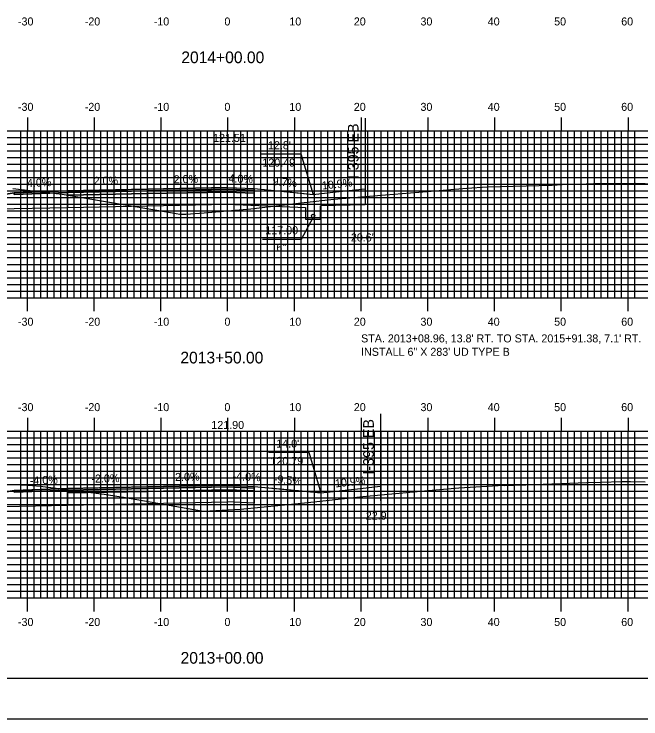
# Model space of a CAD drawing. Extents: x 854287 to 854631, y 366605 to 366825.
# Drawn here: x 854421 to 854515, y 366604.9 to 366710.6 of the extents above; entities that cross this region are included whole.
import ezdxf

# ---------------------------------------------------------------- set-up
doc = ezdxf.new("R2010")
doc.units = 0
for name, color, linetype in [('ANNOTATION', 7, 'Continuous'), ('BORDER', 7, 'Continuous'), ('D_Roadway_Centerline', 7, 'Continuous'), ('D_Roadway_Centerline_Text', 7, 'Continuous'), ('D_Roadway_Edge_Shoulder', 7, 'Continuous'), ('D_Roadway_Edge_TW', 7, 'Continuous'), ('D_Roadway_Pavement', 7, 'Continuous'), ('D_Roadway_SubGrade', 7, 'Continuous'), ('D_Text_Standard', 7, 'Continuous'), ('H_V ANNOTATION', 7, 'Continuous'), ('JUNK', 7, 'Continuous'), ('M_Roadway_Centerline', 7, 'Continuous'), ('MAJOR', 7, 'Continuous'), ('MINOR', 7, 'Continuous'), ('PDRAIN', 7, 'Continuous'), ('PLOT BOUNDARY', 7, 'Continuous'), ('S_Roadway_Centerline', 7, 'Continuous')]:
    doc.layers.add(name, color=color, linetype=linetype)

msp = doc.modelspace()

# ---------------------------------------------------------------- linework, layer by layer
at = {"layer": 'ANNOTATION'}
for points in [[(854458.14, 366689.63), (854464.02, 366689.63), (854465.84, 366683.55)], [(854458.27, 366676.85), (854464.11, 366676.85), (854465.84, 366680.06)], [(854459.19, 366644.93), (854465.21, 366644.93), (854467.02, 366638.84)]]:
    msp.add_lwpolyline(points, dxfattribs=at)
at = {"layer": 'BORDER'}
msp.add_lwpolyline([(854303.44, 366611.06), (854623.44, 366611.06), (854623.44, 366821.06), (854303.44, 366821.06)], close=True, dxfattribs=at)
at = {"layer": 'D_Roadway_Centerline'}
msp.add_line((854453.04, 366682.07), (854464.72, 366681.6), dxfattribs=at)
for points in [[(854403.95, 366680.92), (854421.04, 366683.77), (854421.04, 366683.77), (854429.03, 366684.08), (854429.04, 366684.09), (854438.03, 366684.26), (854441.04, 366684.33), (854441.05, 366684.33), (854453.04, 366684.57), (854457.04, 366684.41), (854463.16, 366683.81), (854465.84, 366683.55)], [(854457.04, 366684.41), (854465.84, 366683.55)], [(854465.84, 366683.55), (854468.83, 366683.87), (854473.67, 366684.4)], [(854473.67, 366681.98), (854466.97, 366681.84)], [(854403.95, 366636.3), (854403.96, 366636.3), (854417.85, 366638.62), (854421.04, 366639.15), (854422.54, 366639.21), (854429.04, 366639.47), (854429.04, 366639.47), (854435.92, 366639.61), (854441.04, 366639.71), (854441.05, 366639.71), (854453.04, 366639.95), (854454.91, 366639.88), (854457.04, 366639.79), (854457.05, 366639.79), (854467.03, 366638.84)], [(854457.04, 366639.79), (854467.01, 366638.85)], [(854467.02, 366638.84), (854472.07, 366639.39), (854475.95, 366639.82)]]:
    msp.add_lwpolyline(points, dxfattribs=at)
at = {"layer": 'D_Roadway_Edge_Shoulder'}
for points in [[(854453.04, 366684.57), (854457.04, 366684.41), (854457.04, 366684.16), (854453.04, 366684.32)], [(854429.04, 366684.09), (854421.04, 366683.77), (854421.04, 366683.52), (854429.04, 366683.84)], [(854429.04, 366639.47), (854421.04, 366639.15), (854421.04, 366638.9), (854429.04, 366639.22)], [(854453.04, 366639.95), (854457.04, 366639.79), (854457.04, 366639.54), (854453.04, 366639.7)]]:
    msp.add_lwpolyline(points, close=True, dxfattribs=at)
at = {"layer": 'D_Roadway_Edge_TW'}
for points in [[(854441.04, 366684.33), (854429.04, 366684.09), (854429.04, 366683.84), (854441.04, 366684.08)], [(854453.04, 366684.57), (854441.04, 366684.33), (854441.04, 366684.08), (854453.04, 366684.32)], [(854441.04, 366639.71), (854429.04, 366639.47), (854429.04, 366639.22), (854441.04, 366639.46)], [(854453.04, 366639.95), (854441.04, 366639.71), (854441.04, 366639.46), (854453.04, 366639.7)]]:
    msp.add_lwpolyline(points, close=True, dxfattribs=at)
at = {"layer": 'D_Roadway_Pavement'}
for points in [[(854441.04, 366684.08), (854429.04, 366683.84), (854429.04, 366683.42), (854441.04, 366683.66)], [(854429.04, 366683.84), (854429.04, 366683.42), (854429.04, 366683.42)], [(854453.04, 366684.32), (854441.04, 366684.08), (854441.04, 366683.66), (854453.04, 366683.9)], [(854453.04, 366684.32), (854457.04, 366684.16), (854457.04, 366683.74), (854453.04, 366683.9)], [(854441.04, 366639.46), (854429.04, 366639.22), (854429.04, 366638.8), (854441.04, 366639.04)], [(854429.04, 366639.22), (854429.04, 366638.8), (854429.04, 366638.8)], [(854453.04, 366639.7), (854441.04, 366639.46), (854441.04, 366639.04), (854453.04, 366639.28)], [(854453.04, 366639.7), (854457.04, 366639.54), (854457.04, 366639.12), (854453.04, 366639.28)]]:
    msp.add_lwpolyline(points, close=True, dxfattribs=at)
for points in [[(854441.04, 366684.08), (854441.04, 366683.66)], [(854441.04, 366639.46), (854441.04, 366639.04)]]:
    msp.add_lwpolyline(points, dxfattribs=at)
at = {"layer": 'D_Roadway_SubGrade'}
for p, q in [((854473.67, 366694.95), (854473.67, 366681.98)), ((854475.95, 366650.64), (854475.95, 366639.82))]:
    msp.add_line(p, q, dxfattribs=at)
for points in [[(854453.04, 366683.9), (854457.04, 366683.74), (854457.04, 366684.16), (854457.04, 366684.41), (854457.04, 366681.91), (854453.04, 366682.07)], [(854429.04, 366683.42), (854429.04, 366683.42), (854429.04, 366683.84), (854421.04, 366683.52), (854421.04, 366683.77), (854405.09, 366681.11), (854429.04, 366681.59)], [(854441.04, 366683.66), (854429.04, 366683.42), (854429.04, 366681.59), (854441.04, 366681.83)], [(854453.04, 366683.9), (854441.04, 366683.66), (854441.04, 366681.83), (854453.04, 366682.07)], [(854429.04, 366638.8), (854429.04, 366638.8), (854429.04, 366639.22), (854421.04, 366638.9), (854421.04, 366639.15), (854405.09, 366636.49), (854429.04, 366636.97)], [(854441.04, 366639.04), (854429.04, 366638.8), (854429.04, 366636.97), (854441.04, 366637.21)], [(854453.04, 366639.28), (854441.04, 366639.04), (854441.04, 366637.21), (854453.04, 366637.45)], [(854453.04, 366639.28), (854457.04, 366639.12), (854457.04, 366639.54), (854457.04, 366639.79), (854457.04, 366637.29), (854453.04, 366637.45)]]:
    msp.add_lwpolyline(points, close=True, dxfattribs=at)
at = {"layer": 'JUNK'}
msp.add_line((854475.95, 366639.82), (854475.95, 366637.61), dxfattribs=at)
at = {"layer": 'MAJOR'}
for p, q in [((854423.04, 366695.06), (854423.04, 366693.06)), ((854433.04, 366695.06), (854433.04, 366693.06)), ((854443.04, 366695.06), (854443.04, 366693.06)), ((854453.04, 366695.06), (854453.04, 366693.06)), ((854463.04, 366695.06), (854463.04, 366693.06)), ((854473.04, 366695.06), (854473.04, 366693.06)), ((854483.04, 366695.06), (854483.04, 366693.06)), ((854493.04, 366695.06), (854493.04, 366693.06)), ((854503.04, 366695.06), (854503.04, 366693.06)), ((854513.04, 366695.06), (854513.04, 366693.06)), ((854313.04, 366693.06), (854593.04, 366693.06)), ((854313.04, 366693.06), (854593.04, 366693.06)), ((854423.04, 366668.06), (854423.04, 366693.06)), ((854433.04, 366668.06), (854433.04, 366693.06)), ((854443.04, 366668.06), (854443.04, 366693.06)), ((854453.04, 366668.06), (854453.04, 366693.06)), ((854463.04, 366668.06), (854463.04, 366693.06)), ((854473.04, 366668.06), (854473.04, 366693.06)), ((854483.04, 366668.06), (854483.04, 366693.06)), ((854493.04, 366668.06), (854493.04, 366693.06)), ((854503.04, 366668.06), (854503.04, 366693.06)), ((854513.04, 366668.06), (854513.04, 366693.06)), ((854313.04, 366688.06), (854593.04, 366688.06)), ((854313.04, 366683.06), (854593.04, 366683.06)), ((854313.04, 366678.06), (854593.04, 366678.06)), ((854313.04, 366673.06), (854593.04, 366673.06)), ((854313.04, 366668.06), (854593.04, 366668.06)), ((854313.04, 366668.06), (854593.04, 366668.06)), ((854423.04, 366666.05), (854423.04, 366668.06)), ((854433.04, 366666.05), (854433.04, 366668.06)), ((854443.04, 366666.05), (854443.04, 366668.06)), ((854453.04, 366666.05), (854453.04, 366668.06)), ((854463.04, 366666.05), (854463.04, 366668.06)), ((854473.04, 366666.05), (854473.04, 366668.06)), ((854483.04, 366666.05), (854483.04, 366668.06)), ((854493.04, 366666.05), (854493.04, 366668.06)), ((854503.04, 366666.05), (854503.04, 366668.06)), ((854513.04, 366666.05), (854513.04, 366668.06)), ((854423.04, 366650.06), (854423.04, 366648.06)), ((854433.04, 366650.06), (854433.04, 366648.06)), ((854443.04, 366650.06), (854443.04, 366648.06)), ((854453.04, 366650.06), (854453.04, 366648.06)), ((854463.04, 366650.06), (854463.04, 366648.06)), ((854473.04, 366650.06), (854473.04, 366648.06)), ((854483.04, 366650.06), (854483.04, 366648.06)), ((854493.04, 366650.06), (854493.04, 366648.06)), ((854503.04, 366650.06), (854503.04, 366648.06)), ((854513.04, 366650.06), (854513.04, 366648.06)), ((854313.04, 366648.06), (854593.04, 366648.06)), ((854313.04, 366648.06), (854593.04, 366648.06)), ((854423.04, 366623.06), (854423.04, 366648.06)), ((854433.04, 366623.06), (854433.04, 366648.06)), ((854443.04, 366623.06), (854443.04, 366648.06)), ((854453.04, 366623.06), (854453.04, 366648.06)), ((854463.04, 366623.06), (854463.04, 366648.06)), ((854473.04, 366623.06), (854473.04, 366648.06)), ((854483.04, 366623.06), (854483.04, 366648.06)), ((854493.04, 366623.06), (854493.04, 366648.06)), ((854503.04, 366623.06), (854503.04, 366648.06)), ((854513.04, 366623.06), (854513.04, 366648.06)), ((854313.04, 366643.06), (854593.04, 366643.06)), ((854313.04, 366638.06), (854593.04, 366638.06)), ((854313.04, 366633.06), (854593.04, 366633.06)), ((854313.04, 366628.06), (854593.04, 366628.06)), ((854313.04, 366623.06), (854593.04, 366623.06)), ((854313.04, 366623.06), (854593.04, 366623.06)), ((854423.04, 366621.05), (854423.04, 366623.06)), ((854433.04, 366621.05), (854433.04, 366623.06)), ((854443.04, 366621.05), (854443.04, 366623.06)), ((854453.04, 366621.05), (854453.04, 366623.06)), ((854463.04, 366621.05), (854463.04, 366623.06)), ((854473.04, 366621.05), (854473.04, 366623.06)), ((854483.04, 366621.05), (854483.04, 366623.06)), ((854493.04, 366621.05), (854493.04, 366623.06)), ((854503.04, 366621.05), (854503.04, 366623.06)), ((854513.04, 366621.05), (854513.04, 366623.06))]:
    msp.add_line(p, q, dxfattribs=at)
at = {"layer": 'MINOR'}
for p, q in [((854422.04, 366668.06), (854422.04, 366693.06)), ((854424.04, 366668.06), (854424.04, 366693.06)), ((854425.04, 366668.06), (854425.04, 366693.06)), ((854426.04, 366668.06), (854426.04, 366693.06)), ((854427.04, 366668.06), (854427.04, 366693.06)), ((854428.04, 366668.06), (854428.04, 366693.06)), ((854429.04, 366668.06), (854429.04, 366693.06)), ((854430.04, 366668.06), (854430.04, 366693.06)), ((854431.04, 366668.06), (854431.04, 366693.06)), ((854432.04, 366668.06), (854432.04, 366693.06)), ((854434.04, 366668.06), (854434.04, 366693.06)), ((854435.04, 366668.06), (854435.04, 366693.06)), ((854436.04, 366668.06), (854436.04, 366693.06)), ((854437.04, 366668.06), (854437.04, 366693.06)), ((854438.04, 366668.06), (854438.04, 366693.06)), ((854439.04, 366668.06), (854439.04, 366693.06)), ((854440.04, 366668.06), (854440.04, 366693.06)), ((854441.04, 366668.06), (854441.04, 366693.06)), ((854442.04, 366668.06), (854442.04, 366693.06)), ((854444.04, 366668.06), (854444.04, 366693.06)), ((854445.04, 366668.06), (854445.04, 366693.06)), ((854446.04, 366668.06), (854446.04, 366693.06)), ((854447.04, 366668.06), (854447.04, 366693.06)), ((854448.04, 366668.06), (854448.04, 366693.06)), ((854449.04, 366668.06), (854449.04, 366693.06)), ((854450.04, 366668.06), (854450.04, 366693.06)), ((854451.04, 366668.06), (854451.04, 366693.06)), ((854452.04, 366668.06), (854452.04, 366693.06)), ((854454.04, 366668.06), (854454.04, 366693.06)), ((854455.04, 366668.06), (854455.04, 366693.06)), ((854456.04, 366668.06), (854456.04, 366693.06)), ((854457.04, 366668.06), (854457.04, 366693.06)), ((854458.04, 366668.06), (854458.04, 366693.06)), ((854459.04, 366668.06), (854459.04, 366693.06)), ((854460.04, 366668.06), (854460.04, 366693.06)), ((854461.04, 366668.06), (854461.04, 366693.06)), ((854462.04, 366668.06), (854462.04, 366693.06)), ((854464.04, 366668.06), (854464.04, 366693.06)), ((854465.04, 366668.06), (854465.04, 366693.06)), ((854466.04, 366668.06), (854466.04, 366693.06)), ((854467.04, 366668.06), (854467.04, 366693.06)), ((854468.04, 366668.06), (854468.04, 366693.06)), ((854469.04, 366668.06), (854469.04, 366693.06)), ((854470.04, 366668.06), (854470.04, 366693.06)), ((854471.04, 366668.06), (854471.04, 366693.06)), ((854472.04, 366668.06), (854472.04, 366693.06)), ((854474.04, 366668.06), (854474.04, 366693.06)), ((854475.04, 366668.06), (854475.04, 366693.06)), ((854476.04, 366668.06), (854476.04, 366693.06)), ((854477.04, 366668.06), (854477.04, 366693.06)), ((854478.04, 366668.06), (854478.04, 366693.06)), ((854479.04, 366668.06), (854479.04, 366693.06)), ((854480.04, 366668.06), (854480.04, 366693.06)), ((854481.04, 366668.06), (854481.04, 366693.06)), ((854482.04, 366668.06), (854482.04, 366693.06)), ((854484.04, 366668.06), (854484.04, 366693.06)), ((854485.04, 366668.06), (854485.04, 366693.06)), ((854486.04, 366668.06), (854486.04, 366693.06)), ((854487.04, 366668.06), (854487.04, 366693.06)), ((854488.04, 366668.06), (854488.04, 366693.06)), ((854489.04, 366668.06), (854489.04, 366693.06)), ((854490.04, 366668.06), (854490.04, 366693.06)), ((854491.04, 366668.06), (854491.04, 366693.06)), ((854492.04, 366668.06), (854492.04, 366693.06)), ((854494.04, 366668.06), (854494.04, 366693.06)), ((854495.04, 366668.06), (854495.04, 366693.06)), ((854496.04, 366668.06), (854496.04, 366693.06)), ((854497.04, 366668.06), (854497.04, 366693.06)), ((854498.04, 366668.06), (854498.04, 366693.06)), ((854499.04, 366668.06), (854499.04, 366693.06)), ((854500.04, 366668.06), (854500.04, 366693.06)), ((854501.04, 366668.06), (854501.04, 366693.06)), ((854502.04, 366668.06), (854502.04, 366693.06)), ((854504.04, 366668.06), (854504.04, 366693.06)), ((854505.04, 366668.06), (854505.04, 366693.06)), ((854506.04, 366668.06), (854506.04, 366693.06)), ((854507.04, 366668.06), (854507.04, 366693.06)), ((854508.04, 366668.06), (854508.04, 366693.06)), ((854509.04, 366668.06), (854509.04, 366693.06)), ((854510.04, 366668.06), (854510.04, 366693.06)), ((854511.04, 366668.06), (854511.04, 366693.06)), ((854512.04, 366668.06), (854512.04, 366693.06)), ((854514.04, 366668.06), (854514.04, 366693.06)), ((854313.04, 366692.06), (854593.04, 366692.06)), ((854313.04, 366691.06), (854593.04, 366691.06)), ((854313.04, 366690.06), (854593.04, 366690.06)), ((854313.04, 366689.06), (854593.04, 366689.06)), ((854313.04, 366687.06), (854593.04, 366687.06)), ((854313.04, 366686.06), (854593.04, 366686.06)), ((854313.04, 366685.06), (854593.04, 366685.06)), ((854313.04, 366684.06), (854593.04, 366684.06)), ((854313.04, 366682.06), (854593.04, 366682.06)), ((854313.04, 366681.06), (854593.04, 366681.06)), ((854313.04, 366680.06), (854593.04, 366680.06)), ((854313.04, 366679.06), (854593.04, 366679.06)), ((854313.04, 366677.06), (854593.04, 366677.06)), ((854313.04, 366676.06), (854593.04, 366676.06)), ((854313.04, 366675.06), (854593.04, 366675.06)), ((854313.04, 366674.06), (854593.04, 366674.06)), ((854313.04, 366672.06), (854593.04, 366672.06)), ((854313.04, 366671.06), (854593.04, 366671.06)), ((854313.04, 366670.06), (854593.04, 366670.06)), ((854313.04, 366669.06), (854593.04, 366669.06)), ((854422.04, 366623.06), (854422.04, 366648.06)), ((854424.04, 366623.06), (854424.04, 366648.06)), ((854425.04, 366623.06), (854425.04, 366648.06)), ((854426.04, 366623.06), (854426.04, 366648.06)), ((854427.04, 366623.06), (854427.04, 366648.06)), ((854428.04, 366623.06), (854428.04, 366648.06)), ((854429.04, 366623.06), (854429.04, 366648.06)), ((854430.04, 366623.06), (854430.04, 366648.06)), ((854431.04, 366623.06), (854431.04, 366648.06)), ((854432.04, 366623.06), (854432.04, 366648.06)), ((854434.04, 366623.06), (854434.04, 366648.06)), ((854435.04, 366623.06), (854435.04, 366648.06)), ((854436.04, 366623.06), (854436.04, 366648.06)), ((854437.04, 366623.06), (854437.04, 366648.06)), ((854438.04, 366623.06), (854438.04, 366648.06)), ((854439.04, 366623.06), (854439.04, 366648.06)), ((854440.04, 366623.06), (854440.04, 366648.06)), ((854441.04, 366623.06), (854441.04, 366648.06)), ((854442.04, 366623.06), (854442.04, 366648.06)), ((854444.04, 366623.06), (854444.04, 366648.06)), ((854445.04, 366623.06), (854445.04, 366648.06)), ((854446.04, 366623.06), (854446.04, 366648.06)), ((854447.04, 366623.06), (854447.04, 366648.06)), ((854448.04, 366623.06), (854448.04, 366648.06)), ((854449.04, 366623.06), (854449.04, 366648.06)), ((854450.04, 366623.06), (854450.04, 366648.06)), ((854451.04, 366623.06), (854451.04, 366648.06)), ((854452.04, 366623.06), (854452.04, 366648.06)), ((854454.04, 366623.06), (854454.04, 366648.06)), ((854455.04, 366623.06), (854455.04, 366648.06)), ((854456.04, 366623.06), (854456.04, 366648.06)), ((854457.04, 366623.06), (854457.04, 366648.06)), ((854458.04, 366623.06), (854458.04, 366648.06)), ((854459.04, 366623.06), (854459.04, 366648.06)), ((854460.04, 366623.06), (854460.04, 366648.06)), ((854461.04, 366623.06), (854461.04, 366648.06)), ((854462.04, 366623.06), (854462.04, 366648.06)), ((854464.04, 366623.06), (854464.04, 366648.06)), ((854465.04, 366623.06), (854465.04, 366648.06)), ((854466.04, 366623.06), (854466.04, 366648.06)), ((854467.04, 366623.06), (854467.04, 366648.06)), ((854468.04, 366623.06), (854468.04, 366648.06)), ((854469.04, 366623.06), (854469.04, 366648.06)), ((854470.04, 366623.06), (854470.04, 366648.06)), ((854471.04, 366623.06), (854471.04, 366648.06)), ((854472.04, 366623.06), (854472.04, 366648.06)), ((854474.04, 366623.06), (854474.04, 366648.06)), ((854475.04, 366623.06), (854475.04, 366648.06)), ((854476.04, 366623.06), (854476.04, 366648.06)), ((854477.04, 366623.06), (854477.04, 366648.06)), ((854478.04, 366623.06), (854478.04, 366648.06)), ((854479.04, 366623.06), (854479.04, 366648.06)), ((854480.04, 366623.06), (854480.04, 366648.06)), ((854481.04, 366623.06), (854481.04, 366648.06)), ((854482.04, 366623.06), (854482.04, 366648.06)), ((854484.04, 366623.06), (854484.04, 366648.06)), ((854485.04, 366623.06), (854485.04, 366648.06)), ((854486.04, 366623.06), (854486.04, 366648.06)), ((854487.04, 366623.06), (854487.04, 366648.06)), ((854488.04, 366623.06), (854488.04, 366648.06)), ((854489.04, 366623.06), (854489.04, 366648.06)), ((854490.04, 366623.06), (854490.04, 366648.06)), ((854491.04, 366623.06), (854491.04, 366648.06)), ((854492.04, 366623.06), (854492.04, 366648.06)), ((854494.04, 366623.06), (854494.04, 366648.06)), ((854495.04, 366623.06), (854495.04, 366648.06)), ((854496.04, 366623.06), (854496.04, 366648.06)), ((854497.04, 366623.06), (854497.04, 366648.06)), ((854498.04, 366623.06), (854498.04, 366648.06)), ((854499.04, 366623.06), (854499.04, 366648.06)), ((854500.04, 366623.06), (854500.04, 366648.06)), ((854501.04, 366623.06), (854501.04, 366648.06)), ((854502.04, 366623.06), (854502.04, 366648.06)), ((854504.04, 366623.06), (854504.04, 366648.06)), ((854505.04, 366623.06), (854505.04, 366648.06)), ((854506.04, 366623.06), (854506.04, 366648.06)), ((854507.04, 366623.06), (854507.04, 366648.06)), ((854508.04, 366623.06), (854508.04, 366648.06)), ((854509.04, 366623.06), (854509.04, 366648.06)), ((854510.04, 366623.06), (854510.04, 366648.06)), ((854511.04, 366623.06), (854511.04, 366648.06)), ((854512.04, 366623.06), (854512.04, 366648.06)), ((854514.04, 366623.06), (854514.04, 366648.06)), ((854313.04, 366647.06), (854593.04, 366647.06)), ((854313.04, 366646.06), (854593.04, 366646.06)), ((854313.04, 366645.06), (854593.04, 366645.06)), ((854313.04, 366644.06), (854593.04, 366644.06)), ((854313.04, 366642.06), (854593.04, 366642.06)), ((854313.04, 366641.06), (854593.04, 366641.06)), ((854313.04, 366640.06), (854593.04, 366640.06)), ((854313.04, 366639.06), (854593.04, 366639.06)), ((854313.04, 366637.06), (854593.04, 366637.06)), ((854313.04, 366636.06), (854593.04, 366636.06)), ((854313.04, 366635.06), (854593.04, 366635.06)), ((854313.04, 366634.06), (854593.04, 366634.06)), ((854313.04, 366632.06), (854593.04, 366632.06)), ((854313.04, 366631.06), (854593.04, 366631.06)), ((854313.04, 366630.06), (854593.04, 366630.06)), ((854313.04, 366629.06), (854593.04, 366629.06)), ((854313.04, 366627.06), (854593.04, 366627.06)), ((854313.04, 366626.06), (854593.04, 366626.06)), ((854313.04, 366625.06), (854593.04, 366625.06)), ((854313.04, 366624.06), (854593.04, 366624.06))]:
    msp.add_line(p, q, dxfattribs=at)
at = {"layer": 'PDRAIN'}
msp.add_lwpolyline([(854464.72, 366681.6), (854464.72, 366679.81), (854466.97, 366679.81), (854466.97, 366681.84)], dxfattribs=at)
msp.add_circle((854465.84, 366680.31), 0.25, dxfattribs=at)
at = {"layer": 'PLOT BOUNDARY'}
msp.add_lwpolyline([(854287.26, 366604.94), (854627.26, 366604.94), (854627.26, 366824.94), (854287.26, 366824.94)], close=True, dxfattribs=at)
at = {"layer": 'S_Roadway_Centerline'}
for points in [[(854420.83, 366684.45), (854425.61, 366683.87), (854428.27, 366683.57), (854444.77, 366680.79), (854445.88, 366680.58), (854446.04, 366680.56), (854446.76, 366680.58), (854449.52, 366680.77), (854456.52, 366681.36), (854464.49, 366682.31), (854468.98, 366682.84), (854476.69, 366683.49), (854484.21, 366684.06), (854485.91, 366684.23), (854488.88, 366684.46), (854491.94, 366684.66), (854501.67, 366684.93), (854503.16, 366685), (854505.65, 366685.08), (854507.87, 366685.15), (854508.64, 366685.16), (854513.66, 366685.18), (854514.19, 366685.21), (854518.36, 366685.08)], [(854417.59, 366640.17), (854422.07, 366640.02), (854423.81, 366639.93), (854424.96, 366639.8), (854434.52, 366638.64), (854437.74, 366638.12), (854446.82, 366636.53), (854449.44, 366636.05), (854449.44, 366636.05), (854454.96, 366636.39), (854464.13, 366637.27), (854473.32, 366638.28), (854482.52, 366639.12), (854487.69, 366639.55), (854494.42, 366639.97), (854494.49, 366639.92), (854497.73, 366640.01), (854506.86, 366640.35), (854508.91, 366640.4), (854512.15, 366640.52), (854513.43, 366640.5), (854515.6, 366640.47)]]:
    msp.add_lwpolyline(points, dxfattribs=at)

# ---------------------------------------------------------------- texts
at = {"layer": 'ANNOTATION'}
for s, height, rotation, p in [('I-395 EB', 1.6, 90, (854472.66, 366685.85)), ('2.0%', 1.2, 1.1458, (854444.97, 366685.2)), ('4.0%', 1.2, 357.7093, (854453.16, 366685.36)), ('4.0%', 1.2, 2.2906, (854422.99, 366684.64)), ('2.0%', 1.2, 1.1457, (854432.97, 366684.96)), ('9.7%', 1.2, 354.4367, (854459.73, 366684.95)), ('10.9%', 1.2, 6.2216, (854467.24, 366684.26)), ('117.00', 1.2, 360, (854458.69, 366677.57)), ('6"', 1.2, 360, (854460.35, 366674.97)), ('I-395 EB', 1.6, 90, (854474.95, 366641.55)), ('-4.0%', 1.2, 2.2906, (854423.42, 366640.05)), ('-2.0%', 1.2, 1.1457, (854432.65, 366640.34)), ('-2.0%', 1.2, 1.1458, (854444.65, 366640.58)), ('-4.0%', 1.2, 357.709, (854453.77, 366640.72)), ('-9.5%', 1.2, 354.575, (854459.92, 366640.33)), ('10.9%', 1.2, 6.2434, (854469.2, 366639.62))]:
    msp.add_text(s, height=height, rotation=rotation, dxfattribs=at).set_placement(p)
for s, p in [("12.8' ", (854459.09, 366690.31)), ('120.49', (854458.25, 366687.71)), ("STA. 2013+08.96, 13.8' RT. TO STA. 2015+91.38, 7.1' RT.", (854473.04, 366661.36)), ('INSTALL 6" X 283\' UD TYPE B', (854473.04, 366659.35)), ("14.0' ", (854460.33, 366645.6)), ('120.79', (854459.46, 366643))]:
    msp.add_text(s, height=1.2, dxfattribs=at).set_placement(p)
at = {"layer": 'D_Roadway_Centerline_Text'}
for s, p in [('121.51', (854450.86, 366691.41)), ('121.90', (854450.6, 366648.39))]:
    msp.add_text(s, height=1.2, dxfattribs=at).set_placement(p)
at = {"layer": 'D_Text_Standard'}
for s, p in [("20.6'", (854471.51, 366676.49)), ("22.9'", (854473.75, 366634.79))]:
    msp.add_text(s, height=1.2, dxfattribs=at).set_placement(p)
at = {"layer": 'H_V ANNOTATION'}
for s, height, p in [('-30', 1.2, (854421.62, 366708.86)), ('-20', 1.2, (854431.63, 366708.86)), ('-10', 1.2, (854441.97, 366708.86)), ('0', 1.2, (854452.56, 366708.86)), ('10', 1.2, (854462.29, 366708.86)), ('20', 1.2, (854471.95, 366708.86)), ('30', 1.2, (854481.94, 366708.86)), ('40', 1.2, (854492.02, 366708.86)), ('50', 1.2, (854501.97, 366708.86)), ('60', 1.2, (854512.02, 366708.86)), ('2014+00.00', 1.75, (854446.1, 366703.21)), ('-30', 1.2, (854421.62, 366696.06)), ('-20', 1.2, (854431.63, 366696.06)), ('-10', 1.2, (854441.97, 366696.06)), ('0', 1.2, (854452.56, 366696.06)), ('10', 1.2, (854462.29, 366696.06)), ('20', 1.2, (854471.95, 366696.06)), ('30', 1.2, (854481.94, 366696.06)), ('40', 1.2, (854492.02, 366696.06)), ('50', 1.2, (854501.97, 366696.06)), ('60', 1.2, (854512.02, 366696.06)), ('-30', 1.2, (854421.62, 366663.86)), ('-20', 1.2, (854431.63, 366663.86)), ('-10', 1.2, (854441.97, 366663.86)), ('0', 1.2, (854452.56, 366663.86)), ('10', 1.2, (854462.29, 366663.86)), ('20', 1.2, (854471.95, 366663.86)), ('30', 1.2, (854481.94, 366663.86)), ('40', 1.2, (854492.02, 366663.86)), ('50', 1.2, (854501.97, 366663.86)), ('60', 1.2, (854512.02, 366663.86)), ('2013+50.00', 1.75, (854445.96, 366658.21)), ('-30', 1.2, (854421.62, 366651.06)), ('-20', 1.2, (854431.63, 366651.06)), ('-10', 1.2, (854441.97, 366651.06)), ('0', 1.2, (854452.56, 366651.06)), ('10', 1.2, (854462.29, 366651.06)), ('20', 1.2, (854471.95, 366651.06)), ('30', 1.2, (854481.94, 366651.06)), ('40', 1.2, (854492.02, 366651.06)), ('50', 1.2, (854501.97, 366651.06)), ('60', 1.2, (854512.02, 366651.06)), ('-30', 1.2, (854421.62, 366618.86)), ('-20', 1.2, (854431.63, 366618.86)), ('-10', 1.2, (854441.97, 366618.86)), ('0', 1.2, (854452.56, 366618.86)), ('10', 1.2, (854462.29, 366618.86)), ('20', 1.2, (854471.95, 366618.86)), ('30', 1.2, (854481.94, 366618.86)), ('40', 1.2, (854492.02, 366618.86)), ('50', 1.2, (854501.97, 366618.86)), ('60', 1.2, (854512.02, 366618.86)), ('2013+00.00', 1.75, (854445.99, 366613.21))]:
    msp.add_text(s, height=height, dxfattribs=at).set_placement(p)
at = {"layer": 'M_Roadway_Centerline'}
for s, p in [('C', (854507.86, 366685.15)), ('L', (854507.87, 366685.14)), ('C', (854514.19, 366685.21)), ('L', (854514.19, 366685.2)), ('C', (854512.14, 366640.52)), ('L', (854512.15, 366640.52)), ('C', (854513.42, 366640.5)), ('L', (854513.43, 366640.49))]:
    msp.add_text(s, height=0.0146, dxfattribs=at).set_placement(p)

doc.saveas('drawing.dxf')
